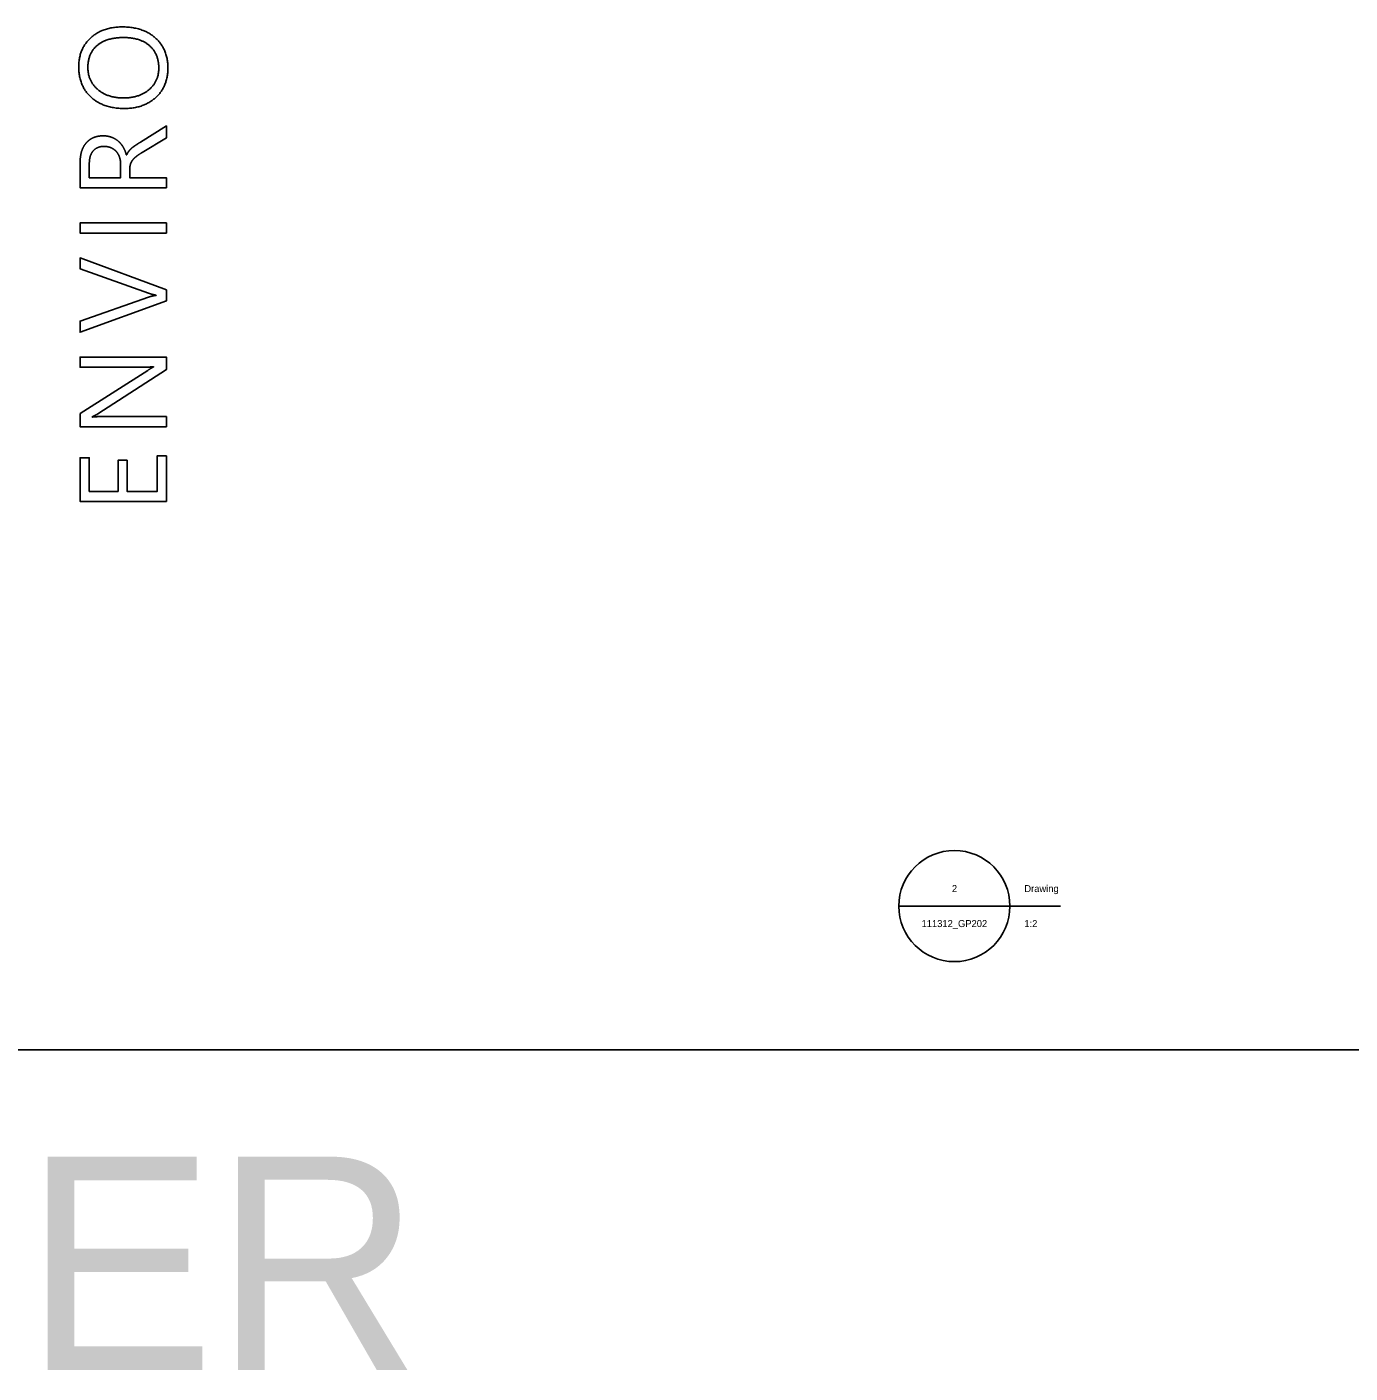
# Model space of a CAD drawing. Extents: x -17 to 34, y -2.3 to 22.
# Drawn here: x 32.564 to 33.184, y 2.349 to 2.979 of the extents above; entities that cross this region are included whole.
import ezdxf

# ---------------------------------------------------------------- set-up
doc = ezdxf.new("R2010")
doc.units = 0
for name, color, linetype in [('CS-ANNO', 7, 'Continuous'), ('CS-ANNO-MATC', 7, 'Continuous'), ('CS-PROF-TEXT', 7, 'Continuous')]:
    doc.layers.add(name, color=color, linetype=linetype)

msp = doc.modelspace()

# ---------------------------------------------------------------- linework, layer by layer
at = {"layer": 'CS-ANNO'}
msp.add_line((32, 2.5), (33.5, 2.5), dxfattribs=at)
at = {"layer": 'CS-ANNO-MATC'}
for p, q in [((32.59253, 2.96045), (32.59253, 2.96045)), ((32.63003, 2.96012), (32.63003, 2.96012)), ((32.61069, 2.9194), (32.61057, 2.9194)), ((32.62456, 2.8536), (32.62456, 2.85371)), ((32.62335, 2.8201), (32.62335, 2.82021)), ((32.59459, 2.79675), (32.59459, 2.79659))]:
    msp.add_line(p, q, dxfattribs=at)
for points in [[(32.61802, 2.92059), (32.62935, 2.92735), (32.62935, 2.93299), (32.6172, 2.92541)], [(32.58892, 2.91608), (32.58892, 2.90401), (32.62935, 2.90401), (32.62935, 2.90875), (32.61215, 2.90875), (32.61215, 2.91264)], [(32.60787, 2.91517), (32.60787, 2.90875), (32.59321, 2.90875), (32.59321, 2.91523)], [(32.62092, 2.85464), (32.58892, 2.86606), (32.58892, 2.87116), (32.62935, 2.85619), (32.62935, 2.85098), (32.58892, 2.83632), (32.58892, 2.84159), (32.62098, 2.85278)], [(32.6174, 2.81993), (32.58892, 2.81993), (32.58892, 2.82467), (32.62935, 2.82467), (32.62935, 2.81886), (32.59713, 2.79805)], [(32.60014, 2.79681), (32.62935, 2.79681), (32.62935, 2.79207), (32.58892, 2.79207), (32.58892, 2.79822), (32.62064, 2.81846)]]:
    msp.add_lwpolyline(points, dxfattribs=at)
for points in [[(32.62935, 2.88753), (32.62935, 2.8828), (32.58892, 2.8828), (32.58892, 2.88753)], [(32.62935, 2.77845), (32.62935, 2.75703), (32.58892, 2.75703), (32.58892, 2.77755), (32.59321, 2.77755), (32.59321, 2.76176), (32.60666, 2.76176), (32.60666, 2.77637), (32.61091, 2.77637), (32.61091, 2.76176), (32.62507, 2.76176), (32.62507, 2.77845)]]:
    msp.add_lwpolyline(points, close=True, dxfattribs=at)
for points in [[(32.60863, 2.9794), (32.59952, 2.9794), (32.59388, 2.97428)], [(32.62428, 2.97416), (32.61853, 2.9794), (32.60863, 2.9794)], [(32.59388, 2.97428), (32.58825, 2.96917), (32.58825, 2.96079)], [(32.5969, 2.97072), (32.60127, 2.97444), (32.60928, 2.97444)], [(32.60928, 2.97444), (32.61709, 2.97444), (32.62143, 2.9706)], [(32.63003, 2.96012), (32.63003, 2.96891), (32.62428, 2.97416)], [(32.59253, 2.96045), (32.59253, 2.967), (32.5969, 2.97072)], [(32.62143, 2.9706), (32.62577, 2.96677), (32.62577, 2.96012)], [(32.58825, 2.96079), (32.58825, 2.95171), (32.59405, 2.94644)], [(32.59713, 2.95011), (32.59253, 2.95408), (32.59253, 2.96045)], [(32.62577, 2.96012), (32.62577, 2.95389), (32.62122, 2.95001)], [(32.62436, 2.94634), (32.63003, 2.95152), (32.63003, 2.96012)], [(32.59405, 2.94644), (32.59986, 2.94117), (32.60962, 2.94117)], [(32.60919, 2.94613), (32.60172, 2.94613), (32.59713, 2.95011)], [(32.62122, 2.95001), (32.61666, 2.94613), (32.60919, 2.94613)], [(32.60962, 2.94117), (32.61869, 2.94117), (32.62436, 2.94634)], [(32.59497, 2.92744), (32.59295, 2.92651), (32.5916, 2.92486)], [(32.59969, 2.92837), (32.59699, 2.92837), (32.59497, 2.92744)], [(32.60357, 2.92773), (32.60181, 2.92837), (32.59969, 2.92837)], [(32.60671, 2.92593), (32.60533, 2.9271), (32.60357, 2.92773)], [(32.58958, 2.92097), (32.58892, 2.91873), (32.58892, 2.91608)], [(32.5916, 2.92486), (32.59025, 2.92321), (32.58958, 2.92097)], [(32.59321, 2.91523), (32.59321, 2.91921), (32.59503, 2.92131)], [(32.59503, 2.92131), (32.59684, 2.92341), (32.60009, 2.92341)], [(32.60009, 2.92341), (32.60189, 2.92341), (32.60334, 2.92279)], [(32.60334, 2.92279), (32.60479, 2.92217), (32.6058, 2.92107)], [(32.6058, 2.92107), (32.6068, 2.91997), (32.60733, 2.91846)], [(32.60907, 2.92311), (32.60809, 2.92476), (32.60671, 2.92593)], [(32.61057, 2.9194), (32.61004, 2.92146), (32.60907, 2.92311)], [(32.61172, 2.92116), (32.61114, 2.92042), (32.61069, 2.9194)], [(32.61308, 2.92259), (32.61229, 2.92191), (32.61172, 2.92116)], [(32.61487, 2.92393), (32.61387, 2.92327), (32.61308, 2.92259)], [(32.6172, 2.92541), (32.61588, 2.92459), (32.61487, 2.92393)], [(32.60733, 2.91846), (32.60787, 2.91695), (32.60787, 2.91517)], [(32.61215, 2.91264), (32.61215, 2.91396), (32.61248, 2.91502)], [(32.61248, 2.91502), (32.6128, 2.91608), (32.61351, 2.91699)], [(32.61351, 2.91699), (32.61421, 2.91791), (32.61533, 2.91878)], [(32.61533, 2.91878), (32.61644, 2.91966), (32.61802, 2.92059)], [(32.62456, 2.85371), (32.62287, 2.85394), (32.62092, 2.85464)], [(32.62098, 2.85278), (32.62253, 2.85332), (32.62456, 2.8536)], [(32.62335, 2.82021), (32.6216, 2.81993), (32.6174, 2.81993)], [(32.62064, 2.81846), (32.62261, 2.81973), (32.62335, 2.8201)], [(32.59713, 2.79805), (32.59591, 2.79726), (32.59459, 2.79675)], [(32.59459, 2.79659), (32.59589, 2.79681), (32.60014, 2.79681)]]:
    msp.add_open_spline(points, degree=2, dxfattribs=at)
at = {"layer": 'CS-PROF-TEXT'}
for p, q in [((32.97244, 2.56742), (33.02452, 2.56742)), ((32.99871, 2.56742), (33.04817, 2.56742))]:
    msp.add_line(p, q, dxfattribs=at)
msp.add_circle((32.99848, 2.56742), 0.02604, dxfattribs=at)

# ---------------------------------------------------------------- texts
at = {"layer": 'CS-ANNO-MATC'}
msp.add_text('DESIGNER', height=0.1, dxfattribs=at).set_placement((32.05, 2.35))
at = {"layer": 'CS-PROF-TEXT'}
for s, height, p in [('2', 0.00328, (32.99733, 2.57398)), ('Drawing', 0.003281, (33.03126, 2.57398)), ('111312_GP202', 0.0032808, (32.98311, 2.55758)), ('1:2', 0.003281, (33.03126, 2.55758))]:
    msp.add_text(s, height=height, dxfattribs=at).set_placement(p)

doc.saveas('drawing.dxf')
